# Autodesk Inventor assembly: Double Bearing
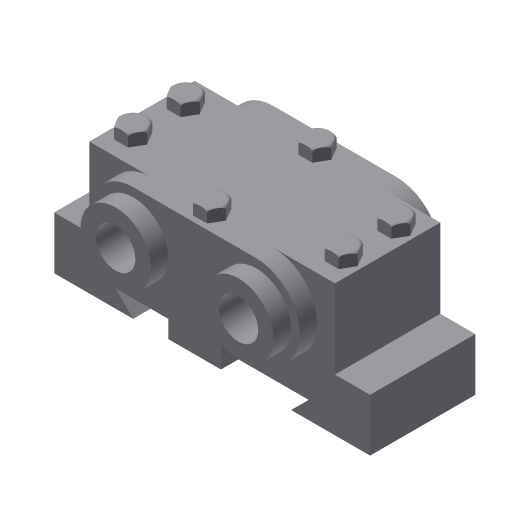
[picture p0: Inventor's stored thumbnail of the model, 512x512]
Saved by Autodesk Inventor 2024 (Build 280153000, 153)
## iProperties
Shininess: 64.0
Length Units: 11269
Angle Units: 11279
Time Units: 11290
Mass Units: 11283
Length Display Precision: 3
Angle Display Precision: 2
Created: 2002-02
Part Number: Double Bearing
Document SubType Name: Assembly
Designer: ***
Density: 0.0
Volumn: 0.0
Area: 0.0
PropertySet Name: Model Information
Control State: 0
Master: False
Checked Out: False
Author: ***
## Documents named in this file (5)
- D:\PROJECTS\Project 2023\RESOURCES INVENTOR 2024\RESOURCES INVENTOR 2024\Inventor_2023_Part\Inventor_2024_Part\c12_Inv_2024_prt\fig-12-10 and 12-18\Double Bearing.iam
- D:\PROJECTS\Project 2023\RESOURCES INVENTOR 2024\RESOURCES INVENTOR 2024\Inventor_2023_Part\Inventor_2024_Part\c12_Inv_2024_prt\fig-12-10 and 12-18\Base.ipt
- D:\PROJECTS\Project 2023\RESOURCES INVENTOR 2024\RESOURCES INVENTOR 2024\Inventor_2023_Part\Inventor_2024_Part\c12_Inv_2024_prt\fig-12-10 and 12-18\Cap.ipt
- D:\PROJECTS\Project 2023\RESOURCES INVENTOR 2024\RESOURCES INVENTOR 2024\Inventor_2023_Part\Inventor_2024_Part\c12_Inv_2024_prt\fig-12-10 and 12-18\Bushing.ipt
- D:\PROJECTS\Project 2023\RESOURCES INVENTOR 2024\RESOURCES INVENTOR 2024\Inventor_2023_Part\Inventor_2024_Part\c12_Inv_2024_prt\fig-12-10 and 12-18\Bolt.ipt
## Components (10 placed, 4 different names)
1. Base:1 — Insert:1, Insert:2
2. Cap:1 — Insert:1, Insert:2, Insert:3, Insert:4, Insert:5, Insert:6
3. Bushing:1 — Insert:3
4. Bushing:2 — Insert:4
5. Bolt:1 — Insert:5
6. Bolt:6
7. Bolt:7
8. Bolt:8
9. Bolt:5 — Insert:6
10. Bolt:9
## Component patterns: Component Pattern 1 (4 elements), Component Pattern 2 (2 elements)
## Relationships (6: Insert 6)
- Insert:1: Base:1 ↔ Cap:1
- Insert:2: Base:1 ↔ Cap:1
- Insert:3: Cap:1 ↔ Bushing:1
- Insert:4: Cap:1 ↔ Bushing:2
- Insert:5: Cap:1 ↔ Bolt:1
- Insert:6: Cap:1 ↔ Bolt:5
